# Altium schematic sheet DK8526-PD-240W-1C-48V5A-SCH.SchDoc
size 584 x 246 mm; SheetNumber: 1; SheetTotal: 1; PageSetup: Record=PageOptions¦CenterHorizontal=True¦CenterVertical=True¦PrintScale=0.37¦XCorrection=1.00¦YCorrection=1.00¦PrintKind=0¦BorderSize=5000000¦LeftOffset=0¦BottomOffset=0¦Orientation=2¦PaperLength=1000¦PaperWidth=1000¦Scale=100¦PaperSource=7¦PrintQuality=-3¦MediaType=1¦DitherType=10¦PrintScaleMode=1¦PaperKind=A4¦PaperIndex=9
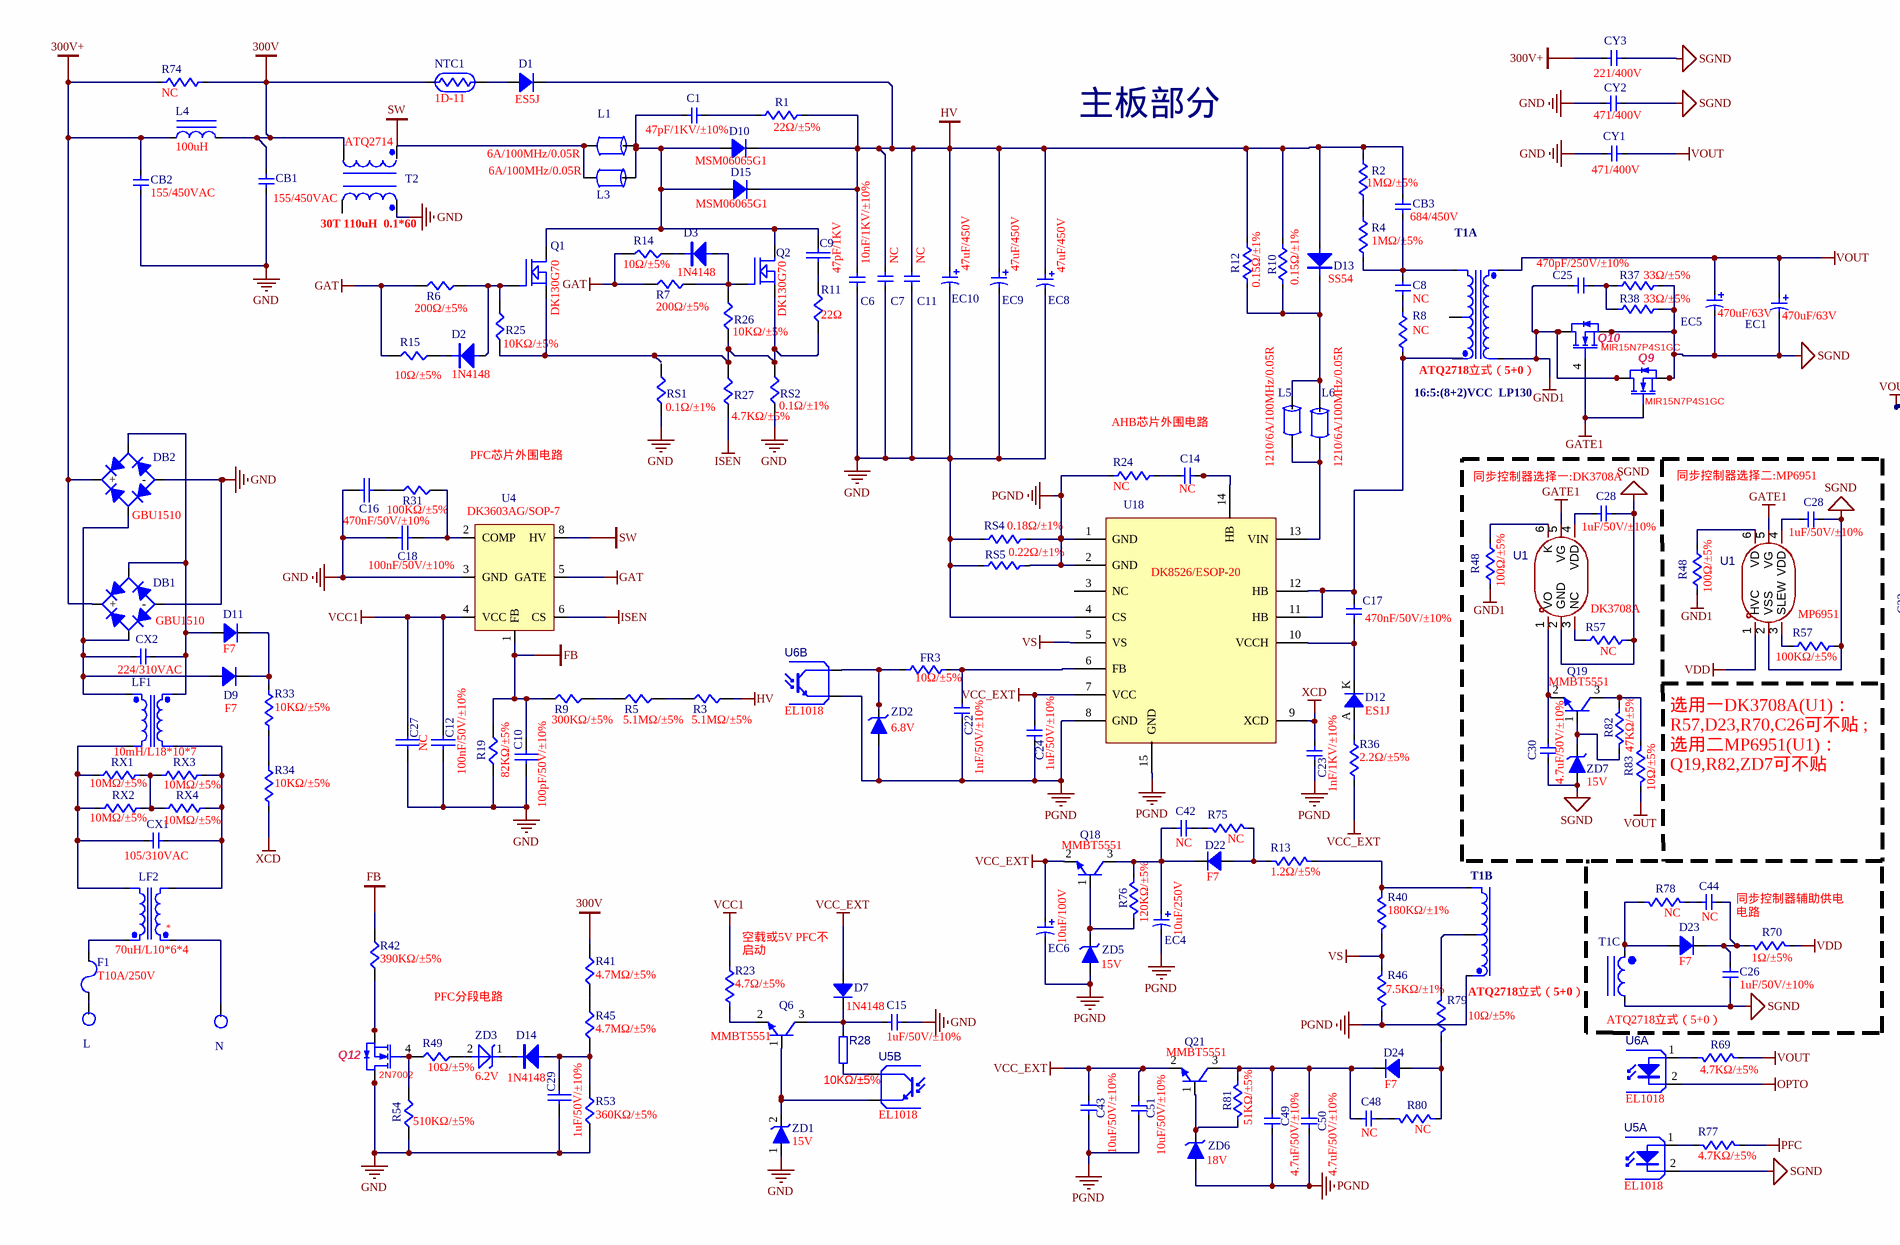
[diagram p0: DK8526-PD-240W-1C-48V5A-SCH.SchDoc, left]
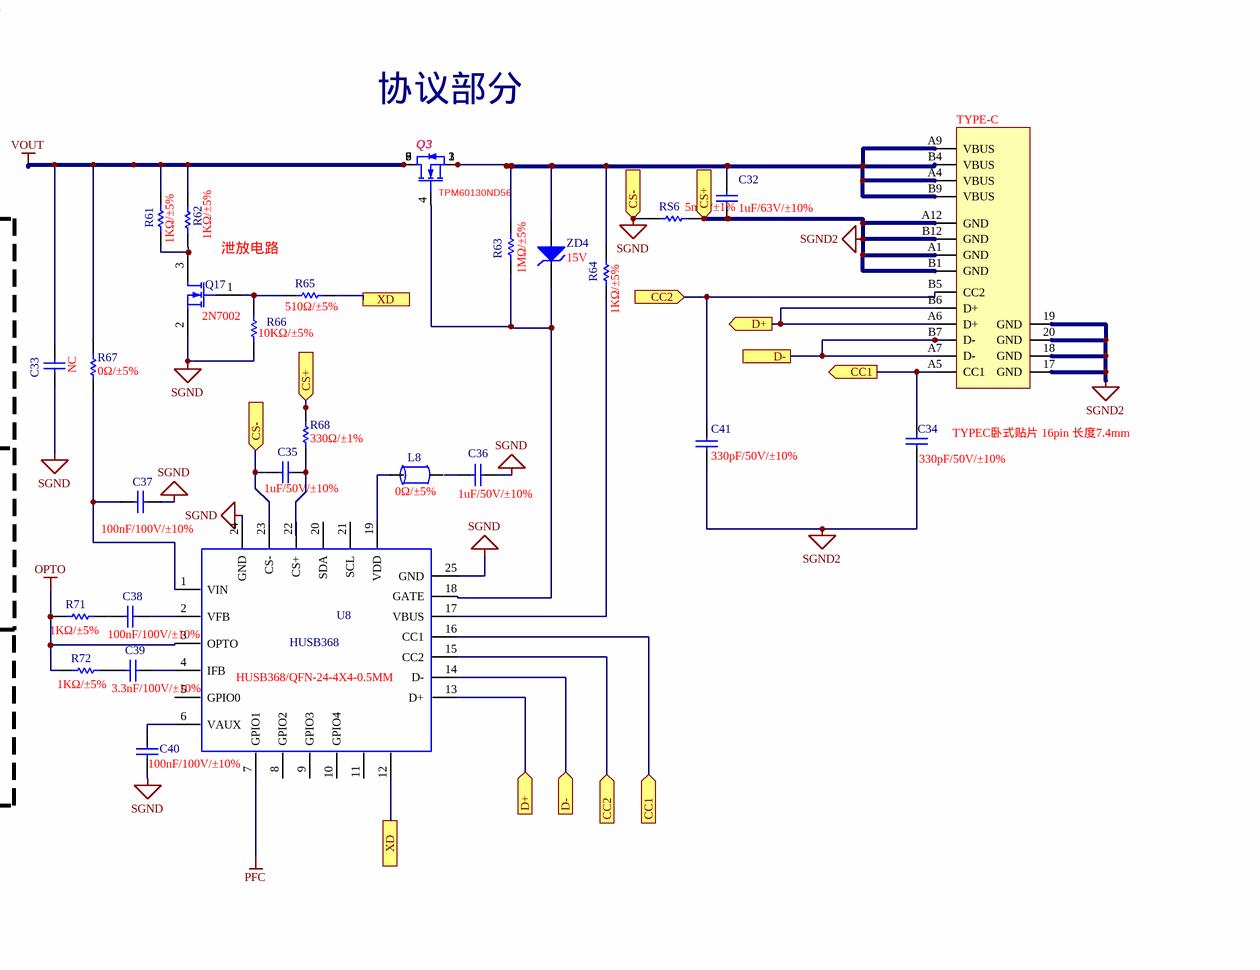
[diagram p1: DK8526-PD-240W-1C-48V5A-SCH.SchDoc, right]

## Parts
(Parts that share a designator on the sheet are numbered #1, #2 ... from top to bottom, then left to right.)
C1  47pF/1KV/±10%  [C1206-1_2]
C6  10nF/1KV/±10%  [C1206-1_2]
C7  NC  [C1206-1_2]
C8  NC  [C1206-1_2]
C9  47pF/1KV  [1812]
C10  100pF/50V/±10%  [1812]
C11  NC  [C1206-1_2]
C12  100nF/50V/±10%  [1812]
C14  NC  [C1206-1_2]
C15  1uF/50V/±10%  [C0603-1]
C16  470nF/50V/±10%  [1812]
C17  470nF/50V/±10%  [C0603-1]
C18  100nF/50V/±10%  [1812]
C22  1nF/50V/±10%  [C0603-1]
C23  1nF/1KV/±10%  [C1206-1_2]
C24  1uF/50V/±10%  [C0603-1_2]
C25  470pF/250V/±10%  [C1206-1_2]
C26  1uF/50V/±10%  [C0603-1]
C27  NC  [1812]
C28#1  1uF/50V/±10%  [C0603-1]
C28#2  1uF/50V/±10%  [C0603-1]
C29  1uF/50V/±10%  [C0603-1_2]
C30  4.7uF/50V/±10%  [C0603-1]
C32  1uF/63V/±10%  [C0603-T_3]
C33  NC  [C0805-1_3]
C34  330pF/50V/±10%  [C0603-T]
C35  1uF/50V/±10%  [C0603-T_3]
C36  1uF/50V/±10%  [C0603-T_3]
C37  100nF/100V/±10%  [C0805-1_3]
C38  100nF/100V/±10%  [C0805-1_3]
C39  3.3nF/100V/±10%  [C0805-1_3]
C40  100nF/100V/±10%  [C0805-1_3]
C41  330pF/50V/±10%  [C0603-T_3]
C42  NC  [C0603-1]
C43  10uF/50V/±10%  [C0603-1]
C44  NC  [C0603-1]
C48  NC  [C0603-1]
C49  4.7uF/50V/±10%  [C0603-1]
C50  4.7uF/50V/±10%  [C0603-1]
C51  10uF/50V/±10%  [C0603-1]
CB1  155/450VAC  [CBB-MPB]
CB2  155/450VAC  [CBB-MPB]
CB3  684/450V  [CAP15]
CX1  105/310VAC  [CX15]
CX2  224/310VAC  [CX15]
CY1  471/400V  [CYP10]
CY2  471/400V  [CYP10]
CY3  221/400V  [CYP10]
D1  ES5J  [SMB]
D2  1N4148  [D-TO-220-2P]
D3  1N4148  [D-TO-220-2P]
D7  1N4148  [SOD-123-标]
D9  F7  [SOD-123-标]
D10  MSM06065G1  [SMC]
D11  F7  [SOD-123-标]
D12  ES1J  [LL-34]
D13  SS54  [D-TO-220-2P]
D14  1N4148  [SOD-123-H]
D15  MSM06065G1  [SMC]
D22  F7  [SOD-123-标]
D23  F7  [SOD-123-标]
D24  F7  [SOD-123-标]
DB1  GBU1510  [HQD3K]
DB2  GBU1510  [HQD3K]
EC1  470uF/63V  [CE10-P5.0MM-AI]
EC4  10uF/250V  [EC18*27_H]
EC5  470uF/63V  [CE10-P5.0MM-AI]
EC6  10uF/100V  [EC18*27_H]
EC8  47uF/450V  [EC18*27_H]
EC9  47uF/450V  [EC18*27_H]
EC10  47uF/450V  [EC18*27_H]
F1  T10A/250V  [FUSE8.5*4]
FR3  10Ω/±5%  [R0603-T]
L  *  [LN]  (value not drawn)
L1  6A/100MHz/0.05R  [1210]
L3  6A/100MHz/0.05R  [1210]
L4  100uH  [L8026]
L5  1210/6A/100MHz/0.05R  [1210]
L6  1210/6A/100MHz/0.05R  [1210]
L8  0Ω/±5%  [R0603-T]
LF1  10mH/L18*10*7  [LF2]
LF2  70uH/L10*6*4  [CHOKE-10MMA]
N  *  [LN]  (value not drawn)
NTC1  1D-11  [THRP7.5]
Q1  DK130G70  [DFN-8X8(Innoscience)]
Q2  DK130G70  [DFN-8X8(Innoscience)]
Q3  TPM60130ND56  [DFN5*6- mos]
Q6  MMBT5551  [SOT-23-T]
Q9  MIR15N7P4S1GC  [DFN5*6- mos]
Q10  MIR15N7P4S1GC  [DFN5*6- mos]
Q12  2N7002  [DFN5*6- mos]
Q17  2N7002  [SOT-23-T_2]
Q18  MMBT5551  [SOT-23-T]
Q19  MMBT5551  [SOT-23-T]
Q21  MMBT5551  [SOT-23-T]
R1  22Ω/±5%  [R1206-T_3]
R2  1MΩ/±5%  [R1206-1_2]
R3  5.1MΩ/±5%  [R1206-H]
R4  1MΩ/±5%  [R1206-1_2]
R5  5.1MΩ/±5%  [R1206-H]
R6  200Ω/±5%  [R1206-H]
R7  200Ω/±5%  [R1206-H]
R8  NC  [R0603-T]
R9  300KΩ/±5%  [R1206-H]
R10  0.15Ω/±1%  [1210L]
R11  22Ω  [R1206-H]
R12  0.15Ω/±1%  [1210L]
R13  1.2Ω/±5%  [R0603-T]
R14  10Ω/±5%  [R1206-H]
R15  10Ω/±5%  [R1206-H]
R19  82KΩ/±5%  [R1206-H]
R23  4.7Ω/±5%  [R0603-T]
R24  NC  [R1206-1_2]
R25  10KΩ/±5%  [R1206-H]
R26  10KΩ/±5%  [R1206-H]
R27  4.7KΩ/±5%  [R1206-H]
R28  10KΩ/±5%  [R0603-T]
R31  100KΩ/±5%  [R1206-H]
R33  10KΩ/±5%  [R1206-锡膏]
R34  10KΩ/±5%  [R1206-锡膏]
R36  2.2Ω/±5%  [R0603-T]
R37  33Ω/±5%  [R1206-T_3]
R38  33Ω/±5%  [R1206-T_3]
R40  180KΩ/±1%  [R0603-T]
R41  4.7MΩ/±5%  [R1206-1_2]
R42  390KΩ/±5%  [R0603-T]
R45  4.7MΩ/±5%  [R1206-1_2]
R46  7.5KΩ/±1%  [R0603-T]
R48#1  100Ω/±5%  [R1206-T_3]
R48#2  100Ω/±5%  [R1206-T_3]
R49  10Ω/±5%  [R0603-T]
R53  360KΩ/±5%  [R0603-T]
R54  510KΩ/±5%  [R0603-T]
R57#1  NC  [R1206-T_2]
R57#2  100KΩ/±5%  [R1206-T_2]
R61  1KΩ/±5%  [R1206-T_3]
R62  1KΩ/±5%  [R1206-T_3]
R63  1MΩ/±5%  [R0603-T]
R64  1KΩ/±5%  [R0603-T_2]
R65  510Ω/±5%  [R0603-T]
R66  10KΩ/±5%  [R0603-T]
R67  0Ω/±5%  [R0603-T]
R68  330Ω/±1%  [R0603-T]
R69  4.7KΩ/±5%  [R0603-T]
R70  1Ω/±5%  [R0603-T]
R71  1KΩ/±5%  [R0603-T]
R72  1KΩ/±5%  [R0603-T]
R74  NC  [R1206-锡膏]
R75  NC  [R0603-T]
R76  120KΩ/±5%  [R0603-T]
R77  4.7KΩ/±5%  [R0603-T]
R78  NC  [R0603-T]
R79  10Ω/±5%  [R0603-T]
R80  NC  [R0603-T]
R81  51KΩ/±5%  [R0603-T]
R82  47KΩ/±5%  [R0603-T]
R83  10Ω/±5%  [R0603-T]
RS1  0.1Ω/±1%  [R1206-H]
RS2  0.1Ω/±1%  [R1206-H]
RS4  0.18Ω/±1%  [R2512]
RS5  0.22Ω/±1%  [R2512]
RS6  5mΩ/±1%  [R1206-T_2 - duplicate]
RX1  10MΩ/±5%  [R1206-锡膏]
RX2  10MΩ/±5%  [R1206-锡膏]
RX3  10MΩ/±5%  [R1206-锡膏]
RX4  10MΩ/±5%  [R1206-锡膏]
T1  ATQ2718立式（5+0）  [POT-4022]  (parts A,B,C of 3)
T2  ATQ2714  [TX-26*16*20 - ATQ - PFC]
TYPE-C  TYPEC卧式贴片 16pin 长度7.4mm  [TYPE-C 卧贴 L6.5mm 沉板1.6mm]
U1#1  DK3708A  [SOT-23-6]
U1#2  MP6951  [SOT-23-6]
U4  DK3603AG/SOP-7  [SO-8]
U5  EL1018  [贴片光耦]  (parts A,B of 2)
U6  EL1018  [贴片光耦]  (parts A,B of 2)
U8  HUSB368/QFN-24-4X4-0.5MM  [QFN-24-4X4-0.5MM]
U18  DK8526/ESOP-20  [8715]
ZD1  15V  [SOD-323]
ZD2  6.8V  [SOD-123]
ZD3  6.2V  [SOD-323]
ZD4  15V  [SOD523]
ZD5  15V  [SOD-123]
ZD6  18V  [SOD-123]
ZD7  15V  [SOD-123]

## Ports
CC1 (in, see DK8526-PD-240W-1C-48V5A-SCH[6B]), CC1 (out, see DK8526-PD-240W-1C-48V5A-SCH[5D]), CC2 (in, see DK8526-PD-240W-1C-48V5A-SCH[5B]), CC2 (in, see DK8526-PD-240W-1C-48V5A-SCH[5D]), CS+ (in, see DK8526-PD-240W-1C-48V5A-SCH[5C]), CS+ (in, see DK8526-PD-240W-1C-48V5A-SCH[6B]), CS- (in, see DK8526-PD-240W-1C-48V5A-SCH[5B]), CS- (in, see DK8526-PD-240W-1C-48V5A-SCH[5C]), D+ (in, see DK8526-PD-240W-1C-48V5A-SCH[6B]), D+ (out, see DK8526-PD-240W-1C-48V5A-SCH[5D]), D- (in, see DK8526-PD-240W-1C-48V5A-SCH[6B]), D- (see DK8526-PD-240W-1C-48V5A-SCH[5D]), XD (see DK8526-PD-240W-1C-48V5A-SCH[5B]), XD (see DK8526-PD-240W-1C-48V5A-SCH[5D])

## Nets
300V: CB1.2 L4.2 NTC1.1 R41.2 R74.1 T2.?3
300V+: CB2.2 CY3.1 DB1.1(+) DB2.1(+) L4.1 R74.2
FB: C10.1 R9.1 R19.2 R42.1 U4.1(FB)
GAT: R6.2 R7.2 R14.1 R15.1 U4.5(GATE)
GATE1: Q9.4(G) Q10.4(G) U1#1.5(VG) U1#2.5(VG)
GND: C6.1 C7.1 C10.2 C11.1 C12.2 C15.1 C16.1 C18.1 C27.2 C29.2 CB1.1 CB2.1 CY1.1 CY2.1 DB1.4(-) DB2.4(-) EC8.1 EC9.1 EC10.1 Q12.5(D) Q12.6(D) Q12.7(D) Q12.8(D) Q12.9(D) R19.1 R53.2 R54.1 RS1.2 RS2.2 RS4.2 RS5.1 T2.?4 U4.3(GND) U18.4(CS) ZD1.1(A)
GND1: C25.2 Q9.5(D) Q9.6(D) Q9.7(D) Q9.8(D) Q9.9(D) Q10.5(D) Q10.6(D) Q10.7(D) Q10.8(D) Q10.9(D) R48#1.2 R48#2.2 T1.7(B)
HV: C6.2 C7.2 C11.2 CB3.2 D1.2(K) D10.2(K) D13.?1 D15.2(K) EC8.2 EC9.2 EC10.2 R1.1 R2.1 R3.2 R10.1 R12.1
ISEN: R27.2 U4.6(CS)
OPTO: R71.1 R72.1 U6.2(K) U8.3(OPTO)
PFC: R77.1 U8.7(GPIO1)
PGND: C22.1 C23.1 C24.1 C43.1 C49.1 C50.1 C51.1 EC4.1 EC6.1 R24.2 R46.1 RS4.1 RS5.2 T1.3 U6.4(E) U18.1(GND) U18.2(GND) U18.8(GND) U18.15(GND) ZD2.1(A) ZD5.1(A) ZD6.1(A)
SGND: C26.1 C28#1.2 C28#2.2 C30.1 C33.1 C35.1 C36.1 C37.2 C40.2 CY2.2 CY3.2 EC1.1 EC5.1 Q9.1(S) Q9.2(S) Q9.3(S) Q10.1(S) Q10.2(S) Q10.3(S) Q17.2(S) R37.2 R38.2 R57#1.1 R57#2.1 R66.1 RS6.2 T1.9 U1#1.2(GND) U1#2.2(VSS) U5.2(K) U8.23(CS-) U8.24(GND) U8.25(GND) ZD7.1(A) ; port CS-
SGND2: C32.1 C34.1 C41.1 R68.1 RS6.1 TYPE-C.17(GND) TYPE-C.18(GND) TYPE-C.19(GND) TYPE-C.20(GND) TYPE-C.A1(GND) TYPE-C.A12(GND) TYPE-C.B1(GND) TYPE-C.B12(GND) ; port CS+
SW: L1.1 L3.1 T2.?2 U4.8(HV)
VCC1: C12.1 C27.1 R23.1 U4.4(VCC)
VCC_EXT: C24.2 C43.2 C51.2 D7.A EC6.2 Q18.2(E) Q21.2(E) R36.1 U18.7(VCC)
VDD: R70.2 U1#2.1(HVC)
VOUT: C33.2 CY1.2 EC1.2 EC5.2 Q3.5(D) Q3.6(D) Q3.7(D) Q3.8(D) Q3.9(D) R61.2 R62.2 R67.1 R69.2 R83.1 T1.6(A)
VS: R40.1 R46.2 U18.5(VS)
XCD: C23.2 R34.1 U18.9(XCD)
CC1: C34.2 TYPE-C.A5(CC1) U8.16(CC1) ; port CC1
CC2: C41.2 TYPE-C.B5(CC2) U8.15(CC2) ; port CC2
D+: TYPE-C.A6(D+) TYPE-C.B6(D+) U8.13(D+) ; port D+
D-: TYPE-C.A7(D-) TYPE-C.B7(D-) U8.14(D-) ; port D-
XD: R65.1 U8.12(GPIO6) ; port XD
NetC1_1: C1.1 R1.2
NetC1_2: C1.2 C9.2 D10.1(A) D15.1(A) L1.2 L3.2 Q1.D Q2.D
NetC8_1: C8.1 CB3.1 R4.2 T1.1
NetC8_2: C8.2 R8.2
NetC9_1: C9.1 R11.1
NetC14_1: C14.1 R24.1
NetC14_2: C14.2 U18.14(HB)
NetC15_2: C15.2 D7.K Q6.3(C) R28.2
NetC16_2: C16.2 R31.2
NetC17_1: C17.1 D12.K U18.10(VCCH)
NetC17_2: C17.2 R8.1 T1.3 U18.11(HB) U18.12(HB)
NetC18_2: C18.2 R31.1 U4.2(COMP)
NetC22_2: C22.2 FR3.2 U18.6(FB)
NetC25_1: C25.1 R37.1 R38.1
NetC26_2: C26.2 C44.1 D23.K R70.1
NetC28#1_1: C28#1.1 U1#1.4(VDD)
NetC28#2_1: C28#2.1 U1#2.4(VDD)
NetC29_1: C29.1 D14.1 R45.1 R53.1
NetC30_2: C30.2 Q19.2(E) U1#1.1(VO)
NetC32_2: C32.2 Q3.1(S) Q3.2(S) Q3.3(S) R63.2 R64.2 TYPE-C.A4(VBUS) TYPE-C.A9(VBUS) TYPE-C.B4(VBUS) TYPE-C.B9(VBUS) ZD4.2(K)
NetC35_2: C35.2 R68.2 U8.22(CS+)
NetC37_1: C37.1 R67.2 U8.1(VIN)
NetC38_1: C38.1 R71.2
NetC38_2: C38.2 U8.2(VFB)
NetC39_1: C39.1 R72.2
NetC39_2: C39.2 U8.4(IFB)
NetC40_1: C40.1 U8.6(VAUX)
NetC42_1: C42.1 R75.1
NetC42_2: C42.2 D22.K EC4.2 Q18.3(C) R76.2
NetC44_2: C44.2 R78.2
NetC48_1: C48.1 R80.1
NetC48_2: C48.2 C49.2 C50.2 D24.K Q21.3(C) R81.2
NetCX1_1: CX1.1 LF1.3 LF2.2 RX3.2 RX4.2
NetCX1_2: CX1.2 LF1.2 LF2.3 RX1.1 RX2.1
NetCX2_1: CX2.1 D11.A DB1.2(AC2) DB2.2(AC2) LF1.4
NetCX2_2: CX2.2 D9.A DB1.3(AC1) DB2.3(AC1) LF1.1
NetD1_1: D1.1(A) NTC1.2
NetD2_2: D2.2 R15.2
NetD2_?1: D2.?1 Q1.G R6.1 R25.1
NetD3_2: D3.2 R14.2
NetD3_?1: D3.?1 Q2.G R7.1 R26.1
NetD9_K: D9.K D11.K R33.2
NetD12_A: D12.A R36.2
NetD13_2: D13.2 L5.2 L6.2 R10.2 R12.2
NetD14_2: D14.2 ZD3.1
NetD22_A: D22.A R13.1 R75.2
NetD23_A: D23.A R78.1 T1.8
NetD24_A: D24.A R79.1 R80.2
NetF1_1: F1.1 L.1
NetF1_2: F1.2 LF2.4
NetFR3_1: FR3.1 U6.3(C) ZD2.2(K)
NetL5_1: L5.1 L6.1 U18.13(VIN)
NetL8_2: L8.2 U8.19(VDD)
NetLF2_1: LF2.1 N.1
NetQ1_S: Q1.S Q2.S R11.2 R25.2 R26.2 R27.1 RS2.1
NetQ3_4: Q3.4(G) R63.1 U8.18(GATE) ZD4.1(A)
NetQ6_1: Q6.1(B) U5.4(E) ZD1.2(K)
NetQ6_2: Q6.2(E) R23.2
NetQ12_1: Q12.1(S) Q12.2(S) Q12.3(S) R42.2
NetQ17_1: Q17.1(G) R65.2 R66.2
NetQ17_3: Q17.3(D) R61.1 R62.1
NetQ18_1: Q18.1(B) R76.1 ZD5.2(K)
NetQ19_1: Q19.1(B) R82.1 ZD7.2(K)
NetQ19_3: Q19.3(C) R82.2 R83.2
NetQ21_1: Q21.1(B) R81.1 ZD6.2(K)
NetR2_2: R2.2 R4.1
NetR3_1: R3.1 R5.2
NetR5_1: R5.1 R9.2
NetR13_2: R13.2 R40.2 T1.1
NetR28_1: R28.1 U5.3(C)
NetR33_1: R33.1 R34.2
NetR41_1: R41.1 R45.2
NetR48#1_1: R48#1.1 U1#1.6(K)
NetR48#2_1: R48#2.1 U1#2.6(VD)
NetR49_1: R49.1 ZD3.2
NetR49_2: R49.2 R54.2
NetR57#1_2: R57#1.2 U1#1.3(NC)
NetR57#2_2: R57#2.2 U1#2.3(SLEW)
NetR64_1: R64.1 U8.17(VBUS)
NetR69_1: R69.1 U6.1(A)
NetR77_2: R77.2 U5.1(A)
NetR79_2: R79.2 T1.2
NetRX1_2: RX1.2 RX2.2 RX3.1 RX4.1

Not connected (* = marked no-connect by the designer): C36 2; L8 1; Q12 4(G); RS1 1; T2 ?1; U8 5(GPIO0) 8(GPIO2) 9(GPIO3) 10(GPIO4) 11(GPIO5) 20(SDA) 21(SCL); U18 3(NC)

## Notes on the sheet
- 主板部分
- (near T2) 30T 110uH  0.1*60
- 协议部分
- 16:5:(8+2)VCC  LP130
- PFC芯片外围电路
- AHB芯片外围电路
- 同步控制器选择一:DK3708A
- 同步控制器选择二:MP6951
- 泄放电路
- 选用一DK3708A(U1)：R57,D23,R70,C26可不贴 ;
  选用二MP6951(U1)：
  Q19,R82,ZD7可不贴
- 同步控制器辅助供电电路
- PFC分段电路
- (near R23) 空载或5V PFC不启动

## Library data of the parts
C1 C6 C7 C11 C14 C23 = CAPACITOR_1206
C8 = CAPACITOR_0603: MLCC Capacitor
C9 C10 C12 C16 C18 C27 C29 = CAP
C15 C17 C22 C24-C26 C28#1 C28#2 C30 C42-C44 C48-C51 CB1-CB3 = CAPACITOR_0603
C32-C41 = Cap: Value: 330pF
CX1 CX2 = CAPACITOR_ XCAP
CY1-CY3 = CAPACITOR_ YCAP
D1 D7 D10-D12 D15 D22-D24 = D0
D2 D3 D13 D14 = DIODE_Y2
D9 = D0: SOD_123
DB1 DB2 = BRIDGE RECTIFIER_SMD
EC1 EC4-EC6 EC8-EC10 = CAPACITOR_EC_D16
F1 = FUSE_BOX
FR3 R2 R4 R8 R10 R12 R13 R23 R24 R36-R38 R40 R46 R69 R70 R75-R83 RS4 RS5 = RESISTOR_0603
L N = TP_1
L1 L5 L6 L8 = BEAD_1
L3 = BEAD_1: BEAD  CORE
L4 = INDUCTOR_ROD TYPE
LF1 LF2 = LINE FILTER_RING CORE
NTC1 = NTC
Q1 Q2 = N-MOS
Q3 Q9 Q10 Q12 Q17 = MOSFET-N
Q6 Q18 Q19 Q21 = 贴片NPN三极管
R1 R33 R34 R74 RX1-RX4 = RESISTOR_1206
R3 R5-R7 R9 R11 R14 R15 R19 R25-R27 R31 R41 R42 R45 R49 R53 R54 RS1 RS2 = RES2
R28 = 贴片电阻
R48#1 R48#2 R57#1 R57#2 = RESISTOR_0805
R61-R63 = Res1: Value: 200R/0805
R64-R68 = Res1: Value: 100K
R71 R72 RS6 = Res1: Value: 10K
T1 = T
T2 = LF-4-7
TYPE-C = TYPE-C-立式
U1#1 U1#2 = MP6908AGJ-Z
U4 = 8PIN IC
U8 = HUSB368
U18 = DK8715AD
ZD1 ZD2 ZD5-ZD7 = ZENER DIODE
ZD3 = ZENER-C
ZD4 = D Zener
